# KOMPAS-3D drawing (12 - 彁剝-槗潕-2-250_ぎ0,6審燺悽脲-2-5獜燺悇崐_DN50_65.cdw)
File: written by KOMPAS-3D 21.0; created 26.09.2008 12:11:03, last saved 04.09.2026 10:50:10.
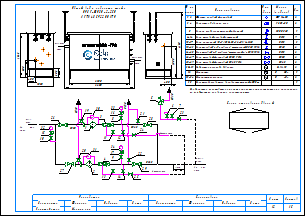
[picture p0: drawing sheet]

Sheets 1-2: A3, landscape

Document properties: Наименование: Макро:21; Автор: RaskoAdmin; Форматы листов документа: 2xA3; Полное имя файла: \\UR38nt01\Departments\КТО\КБ ПУРДГ\Заявки\Прайс-лист на типовые шкафы ГРПШ\ПРДГ_стандарт_20_03_2026\ПРДГ с РДНК\ПРДГ-ШУЭО-2-250_до0,6МПа_Рвых-2-5кПа_РДНК_DN50_65.cdw

Title block, sheet 1: Наименование: Пункт учета газа / ПУГ-Ш-400-Р / ЛГТИ.485922.001ТУ; designation: ЛГТИ.03.4411141; sheet number: 1; Количество листов документа: 2; organisation: ООО "ЭЛЬСТЕР Газэлектроника"; Форматы листов документа: A3; stored path: C:\Рабочие документы\Компас\ПУГ\Схема.cdw; Разработал: Устинов; Проверил: Кошкин; Утвердил: Кошкин
Title block, sheet 2: sheet number: 2; stored path: D:\Рабочие документы\Заявки\ПУРДГ\ПУРДГ-ШУЭО-2-100-Р 4411220.cdw; designation, second copy: ЛГТИ.03.4411141-

Views: Вид 1, Вид 2
Referenced files: wcvoit.frw
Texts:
  Normal
  Вход
  газа
  PDI
  Выход
  Р=     кПа
  DN65
  DN50
  DN20
  Импульс DN15
  ≥5DN
  HYSWLongFangSong
  № на
  схеме
  Усл.
  обозн.
  Марка
  (модель)
  Кол.
  Фильтр газовый фланцевый
  ФГ 16-50
  Регулятор давления газа
  РДНК-50
  Клапан предохранительный сбросной
  КПС DN20
  Кран шаровой газовый латунный
  DN15
  Кран кнопочный VE-РАСКО-НЗ-1,6-G1/2-М20
  Кран шаровой "под приварку" штуцерный DN20 PN16
  Кран шаровой "под приварку" штуцерный п/п DN15 PN16
  Кран шаровой фланцевый DN50 PN16
  Кран шаровой фланцевый DN65 PN16
  Индикатор перепада давления
  Delta 15
  Манометр
  Манометр-напоромер
  Электрообогреватель взрывозащищенный 400Вт
  0...     МПа
  0...     кПа
  Общий вид и габариты шкафа
  ПРДГ-ШУЭО-2-250
  Выход газа
  Вход газа
  Схема открывания дверей
  Р=        МПа
  logo-rasko-ge.png
  Предприятие изготовитель может заменять комплектующие на аналогичные,
  не ухудшающие заявленных характеристик.
  Должность
  Конструктор
  Фамилия
  Подпись
  Дата
  Согласовано
  Максимкин
  Лист
  Листов
  POLYLINE_STYLE_0.18_RGB_0_0_0
  POLYLINE_STYLE_0.50_RGB_0_0_0
  POLYLINE_STYLE_0.34_RGB_0_0_0
  PHANTOM_RGB_0_0_0_SC_1_THICK_0.18
  K5LT_THIN_RGB_0_0_0_THICK_0.18
  K5LT32769_RGB_0_0_0_THICK_0.18
  K5LT12_RGB_0_0_0_SC_1_THICK_0.18
  K5LT_DASHED_RGB_0_0_0_SC_1_THICK_0.18
  ACISOTGL_RGB_0_0_0_SC_0.8_THICK_0.25
  CONTINUOUS_RGB_0_127_31_THICK_0.3
  CONTINUOUS_RGB_0_0_255_THICK_0.35
  CONTINUOUS_RGB_255_0_0_THICK_0.35
  POLYLINE_STYLE_0.25_RGB_0_0_0
  CONTINUOUS_RGB_0_0_0_THICK_0.5
  POLYLINE_STYLE_0.35_RGB_0_0_255
  CONTINUOUS_RGB_0_0_0_THICK_0.4
  CONTINUOUS_RGB_0_0_0_THICK_0.35
  Без оформления
Dimensions and other numbers on the sheet: 1; 2; 3; 4; 5; 10; 27; 28; 29; 23; 8; 12; 19; 20; 21; 22; 25; 24; 30; 31; 15; 16; 26; 6; 7; 11; 14; 13; 33; 1, 2; 3, 4; 6-14; 9; 15-17; 18-23; 24-25; 26-27; 28-29; 30-31; 32; 33-34; 35; 400; 1050; 500; 305; 2300; 1565; 2600; 17; 34; 1000; 4130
